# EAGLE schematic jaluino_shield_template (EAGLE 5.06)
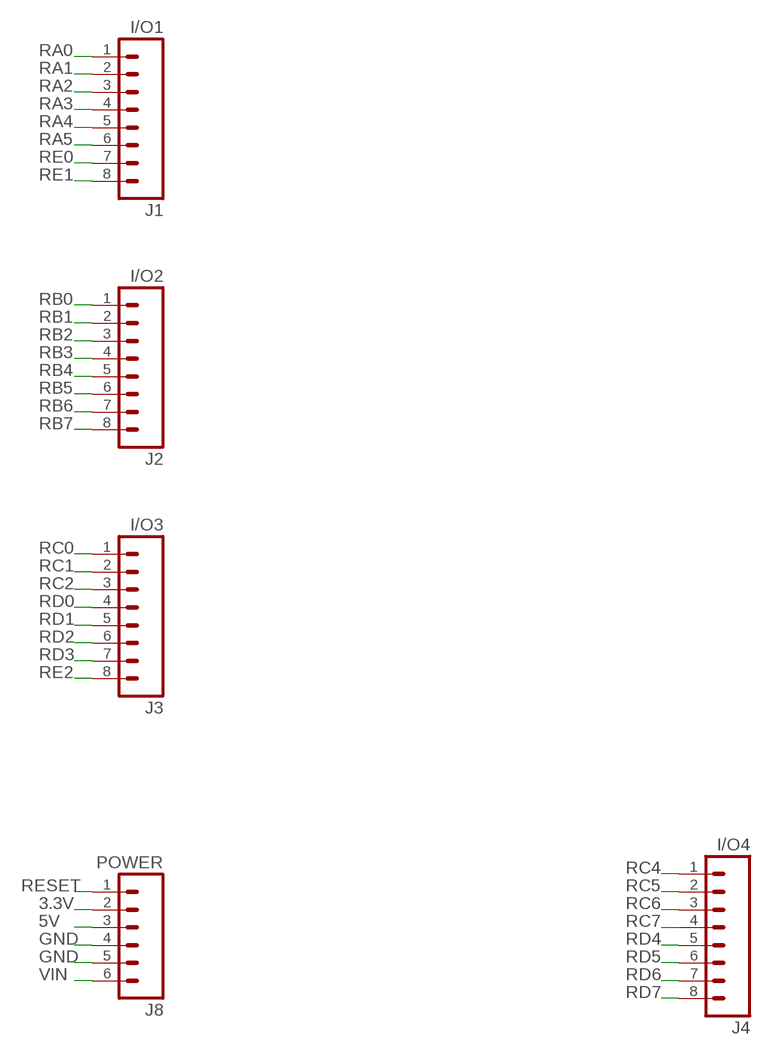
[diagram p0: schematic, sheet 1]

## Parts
J1  I/O1  M08  [1X08]
J2  I/O2  M08  [1X08]
J3  I/O3  M08  [1X08]
J4  I/O4  M08  [1X08]
J8  POWER  M06SIP  [1X06]

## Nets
3.3V: J8.2
5V: J8.3
GND: J8.4 J8.5
RA0: J1.1
RA1: J1.2
RA2: J1.3
RA3: J1.4
RA4: J1.5
RA5: J1.6
RB0: J2.1
RB1: J2.2
RB2: J2.3
RB3: J2.4
RB4: J2.5
RB5: J2.6
RB6: J2.7
RB7: J2.8
RC0: J3.1
RC1: J3.2
RC2: J3.3
RC4: J4.1
RC5: J4.2
RC6: J4.3
RC7: J4.4
RD0: J3.4
RD1: J3.5
RD2: J3.6
RD3: J3.7
RD4: J4.5
RD5: J4.6
RD6: J4.7
RD7: J4.8
RE0: J1.7
RE1: J1.8
RE2: J3.8
RESET: J8.1
VIN: J8.6

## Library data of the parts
J1-J4 = SparkFun:M08: Header 8 Standard 8-pin 0.1" header. Use with straight break away headers (SKU : PRT-00116), right angle break away headers (PRT-00553), swiss pins (PRT-00743), machine pins (PRT-00117), and female headers (PRT-00115).
J8 = SparkFun:M06: Header 6 Standard 6-pin 0.1" header. Use with straight break away headers (SKU : PRT-00116), right angle break away headers (PRT-00553), swiss pins (PRT-00743), machine pins (PRT-00117), and female headers (PRT-00115). Molex polarized connector foot print use with SKU : PRT-08094 with associated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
